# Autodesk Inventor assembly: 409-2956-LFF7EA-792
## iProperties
Created: 2010-09
Part Number: 409-2956-LFF7EA-792
Document SubType Name: Weldment
Designer: S. Boerckel
Weld Material: Welded Aluminum-6061
Mass: 6395.25 g
Surface Area: 2575.35 cm^2
Volume: 811.312 cm^3
Density: 7.88261 g/cm^3
Description: 2" PIPE STAND
User Status: WELD
Material: WELDMENT
SMR: =<MATERIAL>
Author: S. Boerckel
Revision Number: A
